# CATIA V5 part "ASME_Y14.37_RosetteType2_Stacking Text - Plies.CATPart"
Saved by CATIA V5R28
Part number: 333X3333-303
Revision: --
Nomenclature: ASME_Y14.37_RosetteType2
Bounding box of the stored display mesh (mm): x -188.298 to 149.724, y -714.612 to 664.697, z 0 to 93.98
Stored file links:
  C:\Users\jvl2147\Documents\AP242 testing\Composite Example Parts for PER\Stacking Text\ASME_Y14.37_RosetteType2_Stacking Text - Plies.CATPart
  \\NW\Data\MSE-Composites\ASME Y14.37\ASME Y-14.37_COMPOSITES.CATMaterial
  C:\Program Files\Dassault Systemes\B28SP3PRALL\win_b64\startup\composites\LaminateColors.txt
  C:\Program Files\Dassault Systemes\B28SP3PRALL\win_b64\startup\composites\DropOffPattern1BackSlash.txt
  C:\Program Files\Dassault Systemes\B28SP3PRALL\win_b64\startup\composites\DropOffPattern1Backslash.txt
  C:\Program Files\Dassault Systemes\B28SP3PRALL\win_b64\startup\composites\DropOffPattern1InverseV.txt
  C:\Program Files\Dassault Systemes\B28SP3PRALL\win_b64\startup\composites\DropOffPattern1InverseW.txt
  C:\Program Files\Dassault Systemes\B28SP3PRALL\win_b64\startup\composites\DropOffPattern1Slash.txt
  C:\Program Files\Dassault Systemes\B28SP3PRALL\win_b64\startup\composites\DropOffPattern1V.txt
  C:\Program Files\Dassault Systemes\B28SP3PRALL\win_b64\startup\composites\DropOffPattern1V_Symetry.txt
  C:\Program Files\Dassault Systemes\B28SP3PRALL\win_b64\startup\composites\DropOffPattern1V_Symetry_2Consecutive.txt
  C:\Program Files\Dassault Systemes\B28SP3PRALL\win_b64\startup\composites\DropOffPattern1W.txt
  C:\Program Files\Dassault Systemes\B28SP3PRALL\win_b64\startup\composites\DropOffPattern2Cross.txt
  C:\Program Files\Dassault Systemes\B28SP3PRALL\win_b64\startup\composites\DropOffPattern2Diamond.txt
  C:\Program Files\Dassault Systemes\B28SP3PRALL\win_b64\startup\composites\DropOffPattern2Socks.txt
  C:\Program Files\Dassault Systemes\B28SP3PRALL\win_b64\startup\composites\DropOffPattern45AfterOthers.txt
  C:\Program Files\Dassault Systemes\B28SP3PRALL\win_b64\startup\composites\DropOffPattern4TwinDiamonds45.txt
  C:\Program Files\Dassault Systemes\B28SP3PRALL\win_b64\startup\composites\DropOffPattern5Cross_Pseudo_Sym.txt
  C:\Program Files\Dassault Systemes\B28SP3PRALL\win_b64\startup\composites\DropOffPattern5Diamond_Pseudo_Sym.txt
  C:\Program Files\Dassault Systemes\B28SP3PRALL\win_b64\startup\composites\DropOffPattern5Socks_Pseudo_Sym.txt
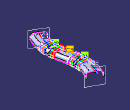
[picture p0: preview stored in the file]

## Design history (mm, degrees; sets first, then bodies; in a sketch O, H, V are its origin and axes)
AxisSystem1 "ROSETTE COORDINATE SYSTEM": origin (-72.9205, -637.9645, 93.98), X (0.5026, 0.8645, 0), Y (-0.8645, 0.5026, 0), Z (0, 0, 1)
CompParametersFeature1 "CATCoParametersFeatName": Value 0, Value 45, Value -45, Value 90
CompEOPGroupFeature1 "CATCoEOPGroupFeatName"
TTRSSet1
CompGridRoot1
CompStacking1 "Stacking"
Set1 "CONSTRUCTION GEOMETRY"
  Set2 "CONSTRUCTION - LAMINATE REFERENCE SURFACE"
    Sketch1 on xy-plane, origin (0, 0, 0), H (1, 0, 0), V (0, 1, 0)
      spline S1 through (-79.505, -649.09) (21.2912, -260.3998) (-51.6257, 228.8061) (37.963, 602.845)
    Plane1: type Normal, Curve Sketch1, RefPoint vertex of Sketch1, Ratio 0
    Sketch2 on Plane1, origin (-464.3095, -417.3341, 0), H (-0.8566, 0.5159, 0), V (0, 0, 1)
      line L1 (-525.4052, 91.6386) -> (-373.0052, 91.6386)
      line L2 (-322.2052, 40.8386) -> (-322.2052, 0)
      line L3 (-576.2052, 0) -> (-576.2052, 40.8386)
      reference projected point E1 (-449.2052, 0) from vertex of Sketch1
      reference projected point E2 (-449.2052, 0) from vertex of Sketch1
      arc A1 centre (-373.0052, 40.8386) radius 50.8 from (-373.0052, 91.6386) to (-322.2052, 40.8386) cw
      arc A2 centre (-525.4052, 40.8386) radius 50.8 from (-576.2052, 40.8386) to (-525.4052, 91.6386) cw
      distance E1 L2 = 127
      distance E2 L3 = 127
      radius A1 = 50.8
      radius A2 = 50.8
      horizontal: L1 H
      vertical: L2 V, L3 V
      tangency: A1 L1, A1 L2, A2 L3, A2 L1
    Sweep1: type Unspec, Profile Sketch2, Guide Sketch1
  Set3 "CONSTRUCTION - PLIES EOPS"
    Plane2: type Normal, Curve Sketch1, RefPoint vertex of Sketch1, Ratio 0
    Plane3: type Normal, Curve Sketch1, RefPoint {point type OnCurve, Support Sketch1, Length 1118.262}, Ratio 0.99
    Plane4: type Normal, Curve Sketch1, Ratio 0.01
    Intersect1: ToIntersect1 Plane3, ToIntersect2 Sweep1
    Intersect2: ToIntersect1 Sweep1, ToIntersect2 Plane4
    Plane5: type Offset, RefPlane xy-plane, Offset 2.54
    Intersect3: ToIntersect1 Plane5, ToIntersect2 Join1
    Near1: MultiElement Intersect3, ReferenceElement edge of Sweep1
    Near2: MultiElement Intersect3, ReferenceElement edge of Sweep1
    CurvePar1: Support Join1, Offset2 0, Offset1 50
  Set4 "CONSTRUCTION - ROSETTE COORDINATE SYSTEM"
    Intersect4: ToIntersect1 Plane4, ToIntersect2 Project1
    Line1: type Tangency, RefPoint Intersect4, Curve Project1, Start 0, End 25.4
    Plane6: type Offset, RefPlane xy-plane, Offset 93.98
    Project1 "CURVE": ToProject Sketch1, Support Plane6
  CurvePar2: Offset Near1, Support Join1, Offset2 0, Offset1 50.8
  Set5 "CONSTRUCTION - GRID"
    Point1: type OnCurve, Support Project2, Length 258.5616 {= length(Project2) / 5}
    Plane7: type Normal, Curve Project2, RefPoint Point1
    Point2: type OnCurve, Support Project2, Length 517.1231 {= (length(Project2)) * 2 / 5}
    Plane8: type Normal, Curve Project2, RefPoint Point2
    Point3: type OnCurve, Support Project2, Length 775.6847 {= (length(Project2)) * 3 / 5}
    Plane9: type Normal, Curve Project2, RefPoint Point3
    Point4: type OnCurve, Support Project2, Length 1034.2463 {= (length(Project2)) * 4 / 5}
    Plane10: type Normal, Curve Project2, RefPoint Point4
    Plane11: type Normal, Curve Sketch1, Ratio 0.01
    Plane12: type Normal, Curve Sketch1, RefPoint {point type OnCurve, Support Sketch1, Length 1118.262}, Ratio 0.99
    Sweep2: type Segment, GuideCrv Near1, GuideSurf Join1, Length1 10, Length2 10, Angle 90
    Sweep3: type Segment, GuideCrv Near2, GuideSurf Join1, Length1 10, Length2 10, Angle 90
    CurvePar3: Support Join1, Offset2 0, Offset1 20
    CurvePar4: Support Join1, Offset2 0, Offset1 1
    CurvePar5: Support Join1, Offset2 0, Offset1 1
Set6 "ENGINEERING GEOMETRY"
  Set7 "LAMINATE REFERENCE SURFACE"
    Join1 "LAMINATE REFERENCE SURFACE": Elements Sweep1
  Set8 "GUIDE CURVE - ZERO DEGREE ORIENTATION"
    Project2 "0° GUIDE CURVE": ToProject Sketch1, Support Join1, Direction xy-plane
  Set9 "LLAI - NO DROP OFF ZONE"
    CompStdContourFeature1 "LLAI - NO DROP OFF ZONE BOUNDARY 1": SupportSurface Join1, ClosedSetOfCurves (CurvePar4; {curvepar Support Join1, Offset2 0, Offset1 20}; CurvePar5; CurvePar3), ExtrapolDist 0.2
    CompGridNoDropOffArea1 "LLAI - NO DROP OFF ZONE 1": NoDropOffContour CompStdContourFeature1
    CompStdContourFeature2 "LLAI - NO DROP OFF ZONE BOUNDARY 2": SupportSurface Join1, ClosedSetOfCurves (CurvePar1; CurvePar4; CurvePar5), ExtrapolDist 0.2
    CompGridNoDropOffArea2 "LLAI - NO DROP OFF ZONE 2": NoDropOffContour CompStdContourFeature2
Set10 "Top Surface from Virtual Stackings"
  CompIsoThickAreasTopSurface1 "CATCoIsoThickAreasTopSurfaceFeatName": ListITAs ({datumsurface}; {datumsurface}; {datumsurface}; {datumsurface}; {datumsurface}), ListRampContours ({datumcurve}; {datumcurve}; {datumcurve}; {datumcurve})
Body1 "-303" (main body)
  ThickSurface1: BotOffset 0, Surface CompIsoThickAreasTopSurface1, TopOffset 2
  Split1: SplitPlane Join1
